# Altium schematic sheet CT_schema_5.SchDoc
size 520 x 457 mm
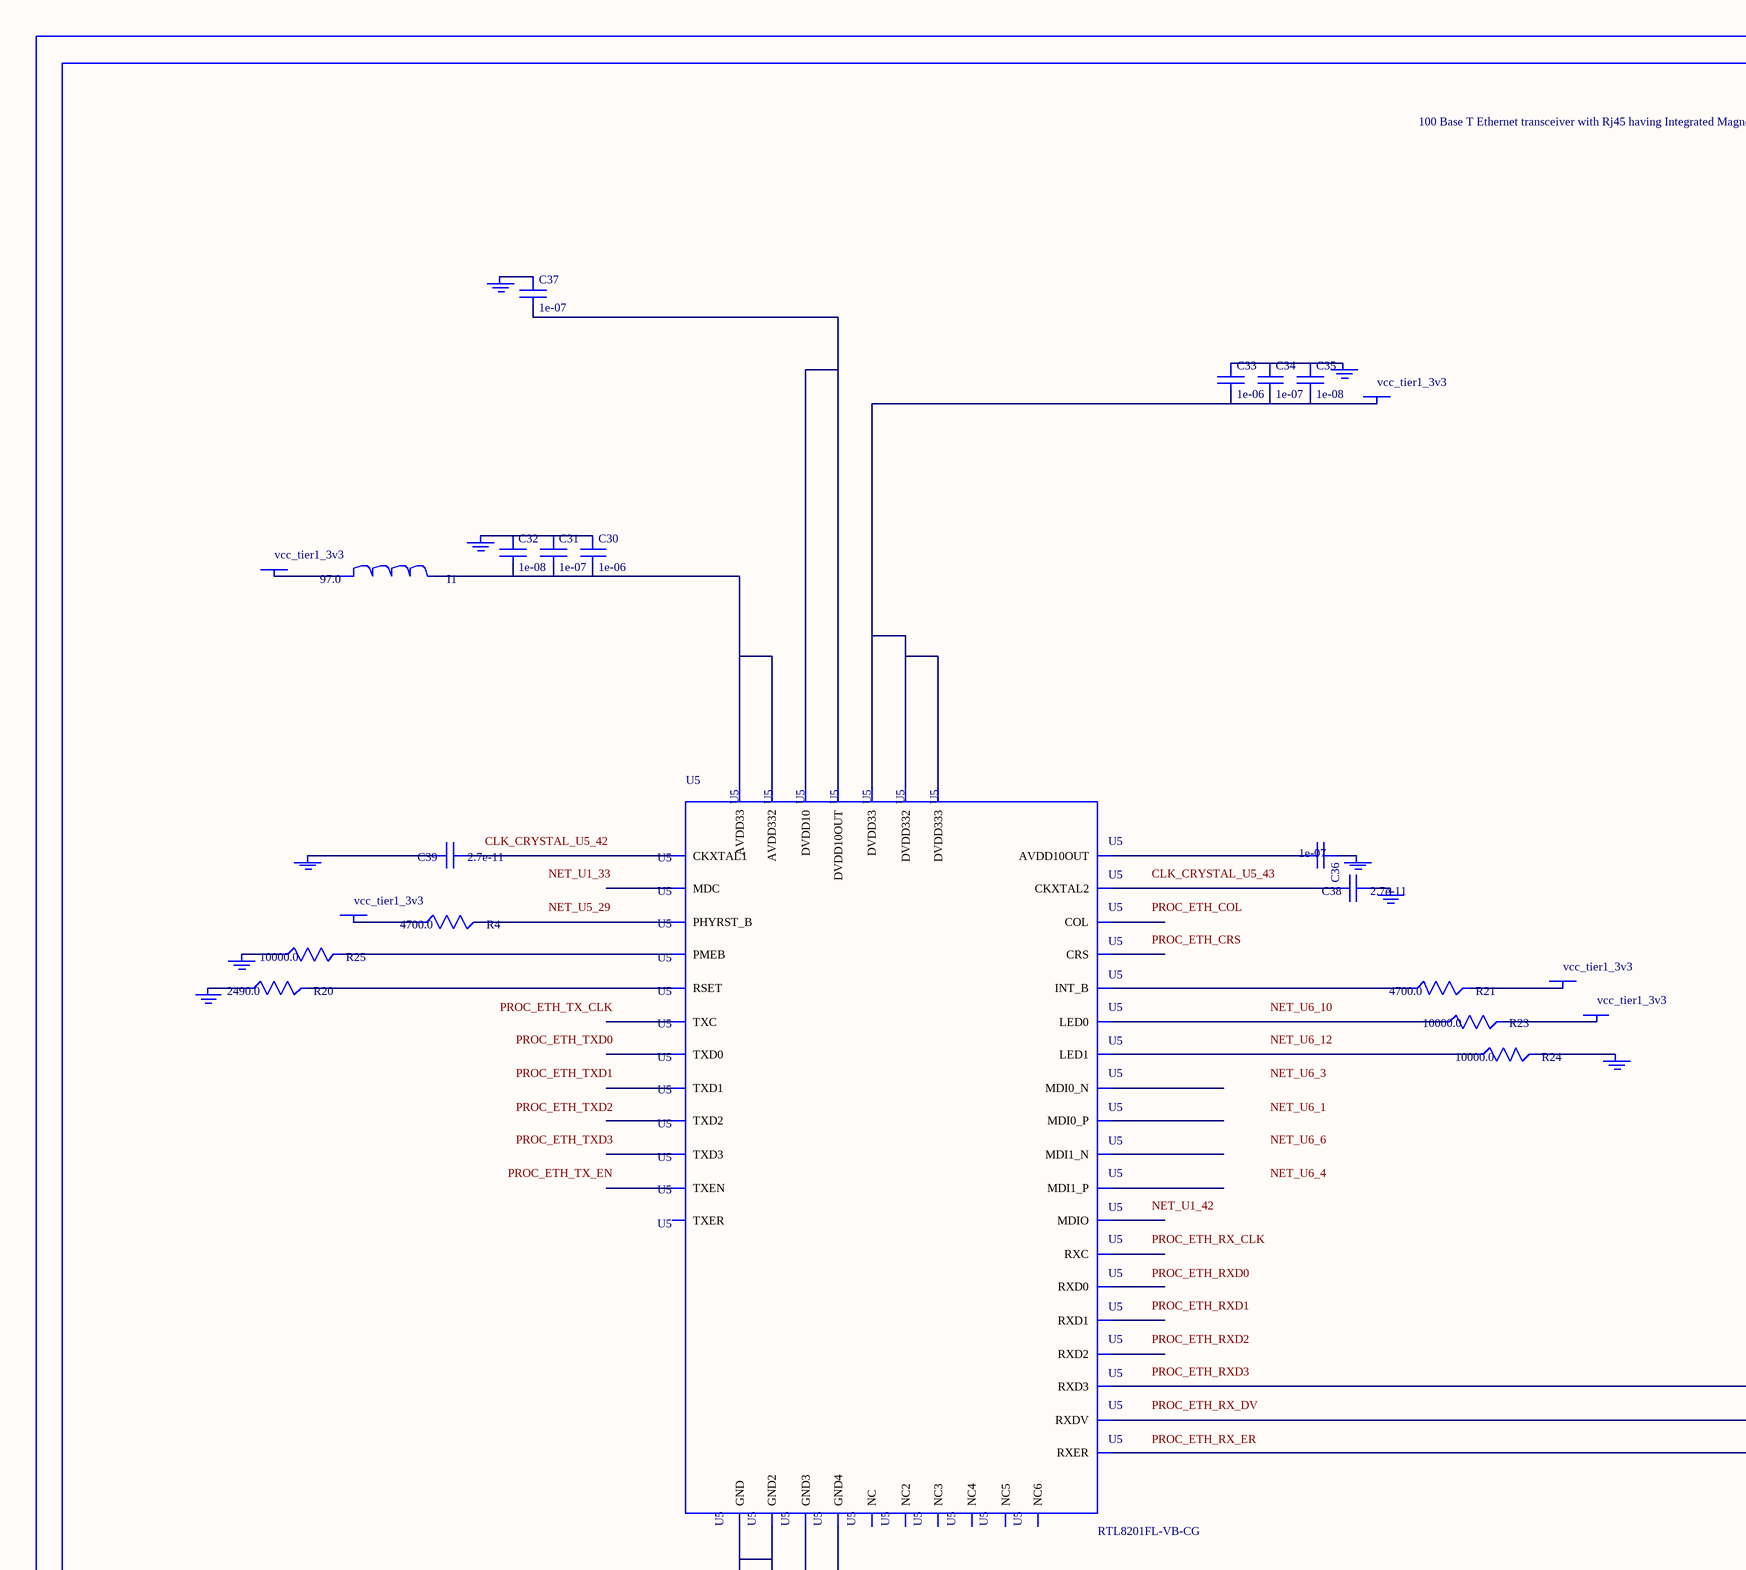
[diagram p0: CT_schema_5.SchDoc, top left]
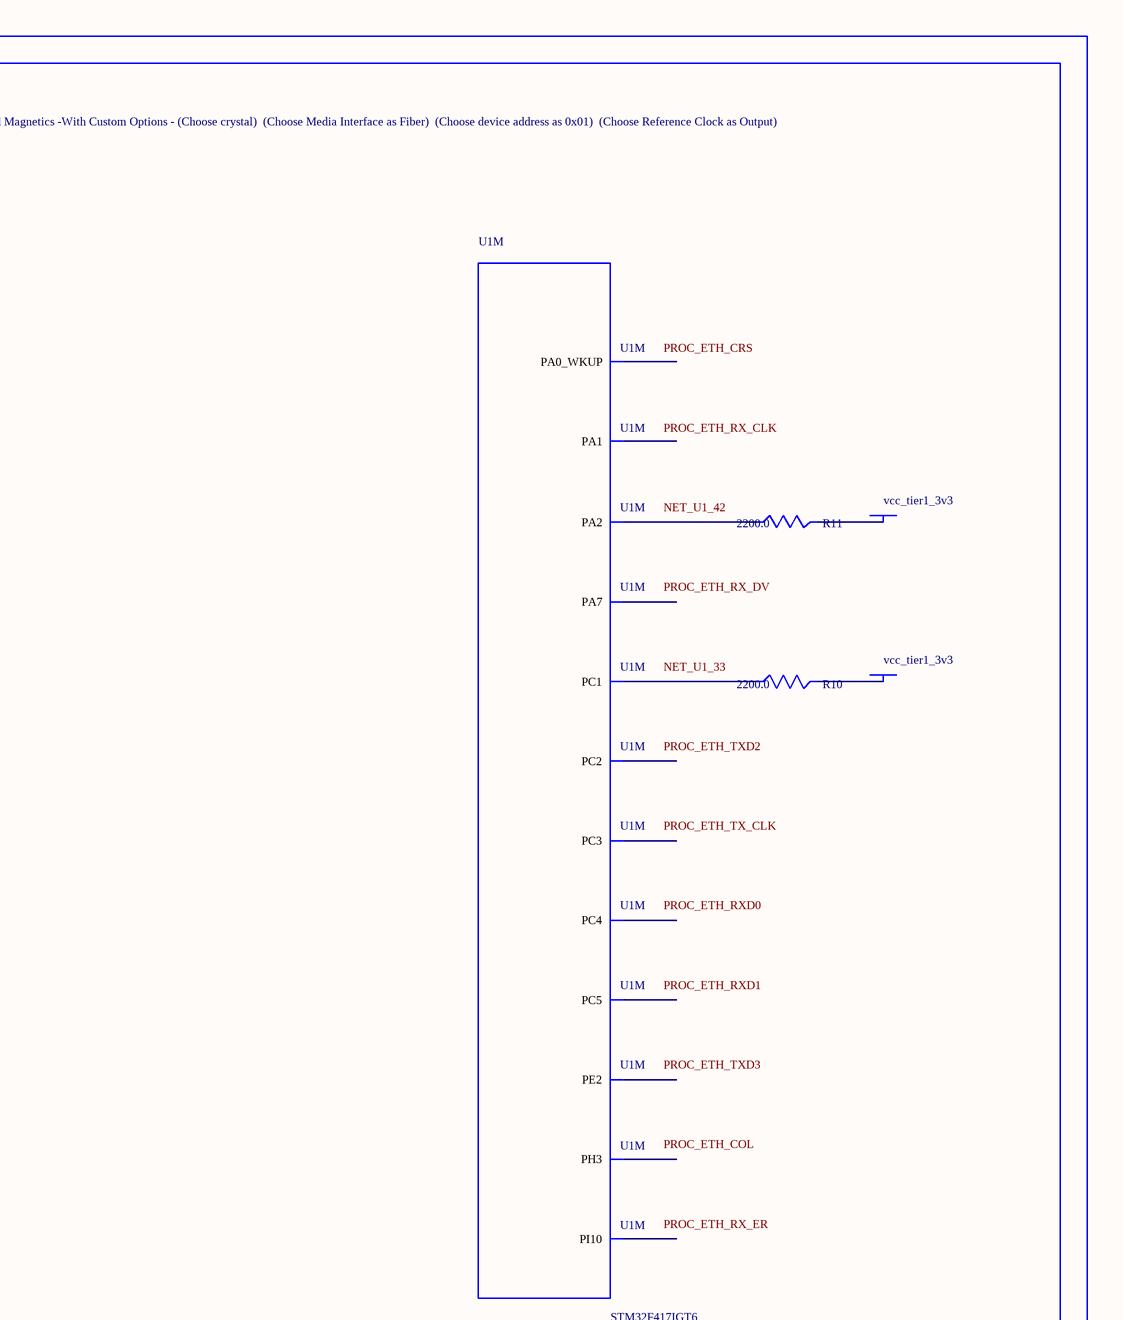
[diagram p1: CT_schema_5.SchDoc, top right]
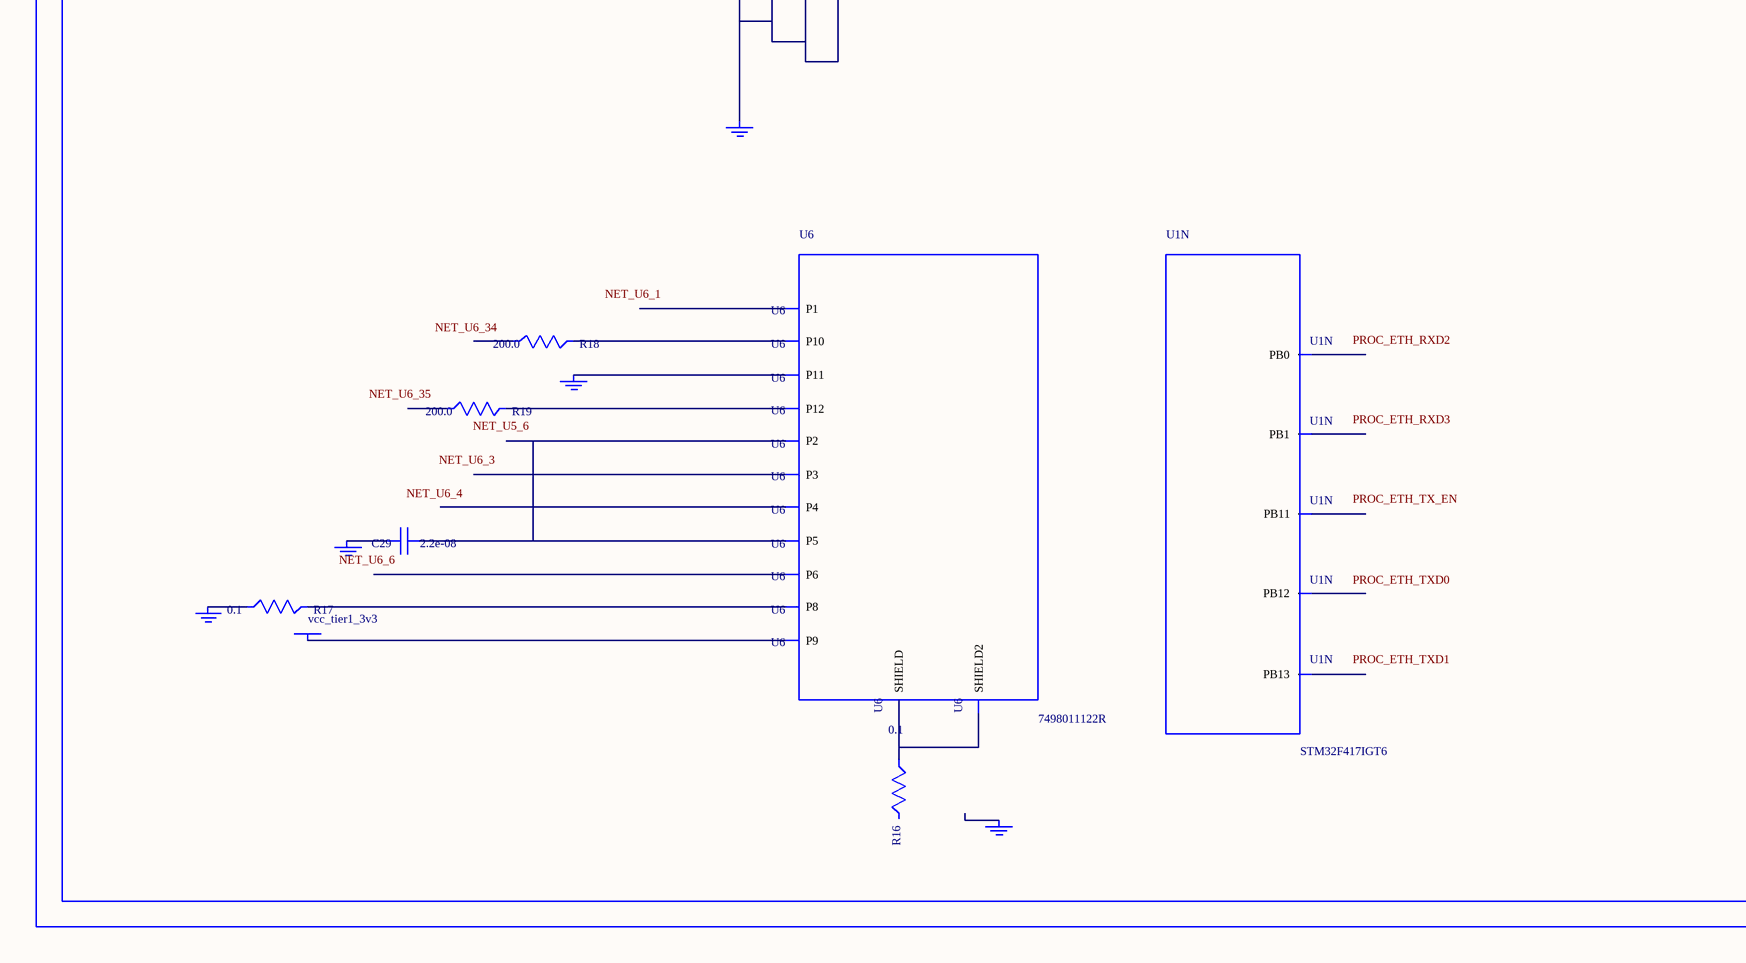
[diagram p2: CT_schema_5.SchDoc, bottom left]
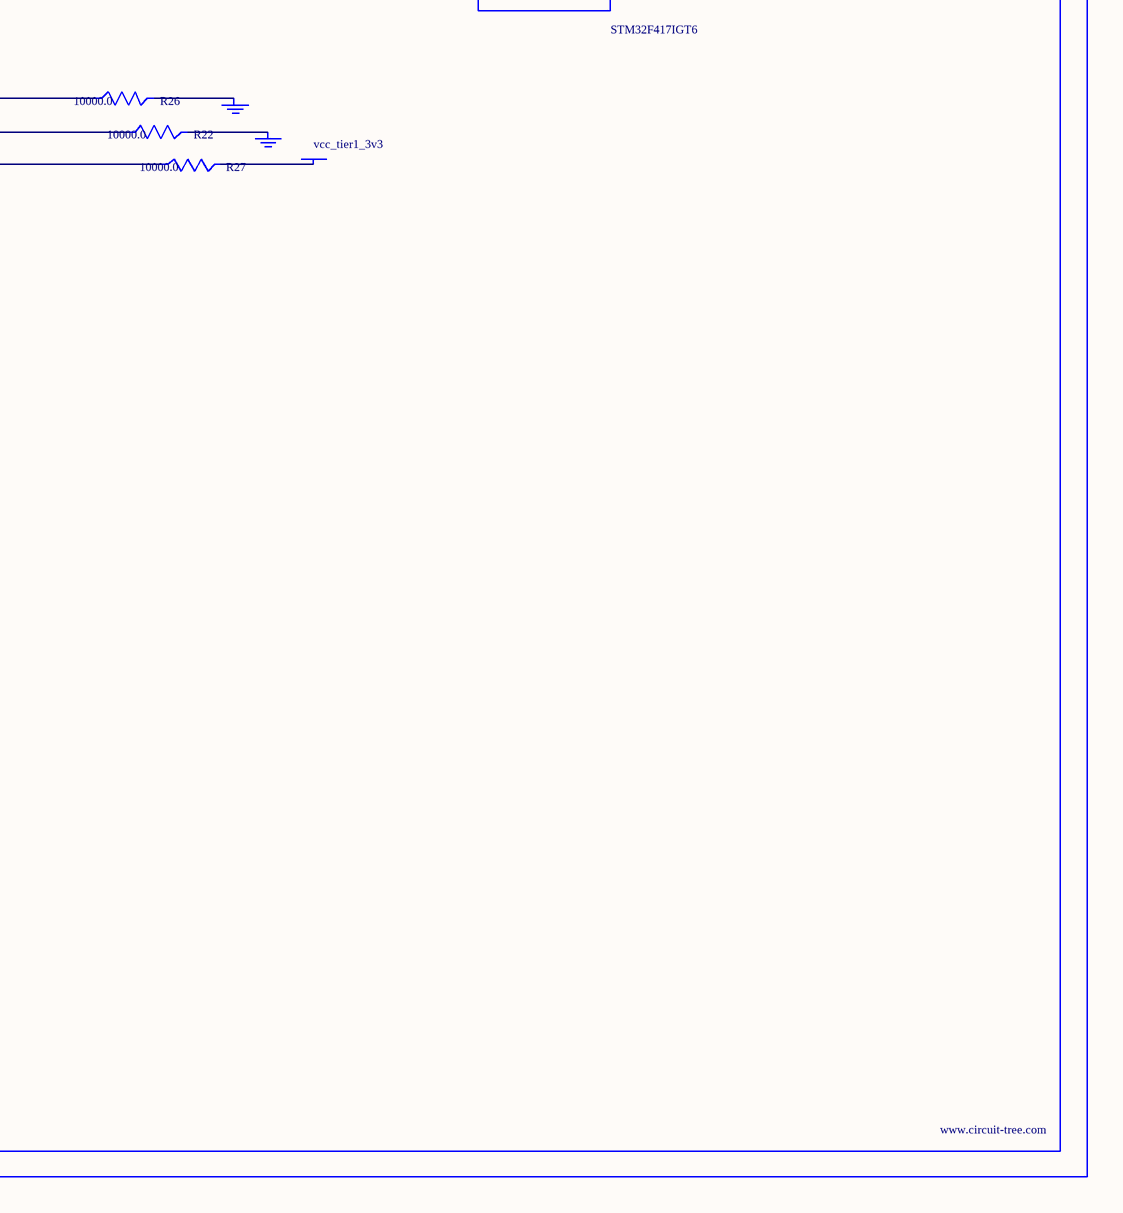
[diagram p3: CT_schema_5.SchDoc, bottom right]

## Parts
BORDER4  (no value)
C29  2.2e-08  [C0402]
C30  1e-06  [C0603]
C31  1e-07  [C0402]
C32  1e-08  [C0402]
C33  1e-06  [C0603]
C34  1e-07  [C0402]
C35  1e-08  [C0402]
C36  1e-07  [C0402]
C37  1e-07  [C0402]
C38  2.7e-11  [C0402]
C39  2.7e-11  [C0402]
GND_INSTANCE_4_0  (no value)
GND_INSTANCE_4_1  (no value)
GND_INSTANCE_4_2  (no value)
GND_INSTANCE_4_3  (no value)
GND_INSTANCE_4_4  (no value)
GND_INSTANCE_4_5  (no value)
GND_INSTANCE_4_6  (no value)
GND_INSTANCE_4_7  (no value)
GND_INSTANCE_4_8  (no value)
GND_INSTANCE_4_9  (no value)
GND_INSTANCE_4_10  (no value)
GND_INSTANCE_4_11  (no value)
GND_INSTANCE_4_12  (no value)
GND_INSTANCE_4_13  (no value)
GND_INSTANCE_4_14  (no value)
GND_INSTANCE_4_15  (no value)
I1  97.0  [R0603]
POWER_INSTANCE_4_0  vcc_tier1_3v3
POWER_INSTANCE_4_1  vcc_tier1_3v3
POWER_INSTANCE_4_2  vcc_tier1_3v3
POWER_INSTANCE_4_3  vcc_tier1_3v3
POWER_INSTANCE_4_4  vcc_tier1_3v3
POWER_INSTANCE_4_5  vcc_tier1_3v3
POWER_INSTANCE_4_6  vcc_tier1_3v3
POWER_INSTANCE_4_7  vcc_tier1_3v3
POWER_INSTANCE_4_8  vcc_tier1_3v3
R4  4700.0  [R0603]
R10  2200.0  [R0603]
R11  2200.0  [R0603]
R16  0.1  [R0603]
R17  0.1  [R0603]
R18  200.0  [R0603]
R19  200.0  [R0603]
R20  2490.0  [R0603]
R21  4700.0  [R0603]
R22  10000.0  [R0603]
R23  10000.0  [R0603]
R24  10000.0  [R0603]
R25  10000.0  [R0603]
R26  10000.0  [R0603]
R27  10000.0  [R0603]
U1  STM32F417IGT6  [LQFP176]  (parts M,N of 16)
U5  RTL8201FL-VB-CG  [RTL8201FL-VB-CG]
U6  7498011122R  [7498011122R]

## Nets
NetC29_1: C29.1 U6.2(P2) U6.5(P5)
NetC29_2: C29.2 GND_INSTANCE_4_12.0(GND)
NetC30_1: C30.1 C31.1 C32.1 GND_INSTANCE_4_0.0(GND)
NetC30_2: C30.2 C31.2 C32.2 I1.2 U5.6(AVDD33) U5.41(AVDD332)
NetC33_1: C33.1 C34.1 C35.1 GND_INSTANCE_4_3.0(GND)
NetC33_2: C33.2 C34.2 C35.2 POWER_INSTANCE_4_1.0(PWR) U5.15(DVDD33) U5.21(DVDD332) U5.37(DVDD333)
NetC36_1: C36.1 GND_INSTANCE_4_10.0(GND)
NetC36_2: C36.2 U5.48(AVDD10OUT)
NetC37_1: C37.1 GND_INSTANCE_4_6.0(GND)
NetC37_2: C37.2 U5.28(DVDD10) U5.40(DVDD10OUT)
NetC38_1: C38.1 GND_INSTANCE_4_8.0(GND)
NetC38_2: C38.2 U5.43(CKXTAL2)
NetC39_1: C39.1 U5.42(CKXTAL1)
NetC39_2: C39.2 GND_INSTANCE_4_7.0(GND)
NetGND_INSTANCE_4_1_0: GND_INSTANCE_4_1.0(GND) R25.1
NetGND_INSTANCE_4_2_0: GND_INSTANCE_4_2.0(GND) R22.2
NetGND_INSTANCE_4_4_0: GND_INSTANCE_4_4.0(GND) R26.2
NetGND_INSTANCE_4_5_0: GND_INSTANCE_4_5.0(GND) R24.2
NetGND_INSTANCE_4_9_0: GND_INSTANCE_4_9.0(GND) R20.1
NetGND_INSTANCE_4_11_0: GND_INSTANCE_4_11.0(GND) U5.7(GND) U5.20(GND2) U5.33(GND3) U5.47(GND4)
NetGND_INSTANCE_4_13_0: GND_INSTANCE_4_13.0(GND) R17.1
NetGND_INSTANCE_4_14_0: GND_INSTANCE_4_14.0(GND) U6.11(P11)
NetI1_1: I1.1 POWER_INSTANCE_4_0.0(PWR)
NetPOWER_INSTANCE_4_2_0: POWER_INSTANCE_4_2.0(PWR) R21.2
NetPOWER_INSTANCE_4_3_0: POWER_INSTANCE_4_3.0(PWR) R23.2
NetPOWER_INSTANCE_4_4_0: POWER_INSTANCE_4_4.0(PWR) R27.2
NetPOWER_INSTANCE_4_5_0: POWER_INSTANCE_4_5.0(PWR) R4.1
NetPOWER_INSTANCE_4_6_0: POWER_INSTANCE_4_6.0(PWR) R10.2
NetPOWER_INSTANCE_4_7_0: POWER_INSTANCE_4_7.0(PWR) R11.2
NetPOWER_INSTANCE_4_8_0: POWER_INSTANCE_4_8.0(PWR) U6.9(P9)
NetR4_2: R4.2 U5.29(PHYRST_B)
NetR10_1: R10.1 U1.33(PC1)
NetR11_1: R11.1 U1.42(PA2)
NetR16_1: R16.1 U6.13(SHIELD) U6.14(SHIELD2)
NetR17_2: R17.2 U6.8(P8)
NetR18_2: R18.2 U6.10(P10)
NetR19_2: R19.2 U6.12(P12)
NetR20_2: R20.2 U5.46(RSET)
NetR21_1: R21.1 U5.32(INT_B)
NetR22_1: R22.1 U5.13(RXDV)
NetR23_1: R23.1 U5.34(LED0)
NetR24_1: R24.1 U5.35(LED1)
NetR25_2: R25.2 U5.10(PMEB)
NetR26_1: R26.1 U5.18(RXD3)
NetR27_1: R27.1 U5.39(RXER)

Not connected (* = marked no-connect by the designer): GND_INSTANCE_4_15 0(GND); R16 2; R18 1; R19 1; U1 1(PE2) 12(PI10) 34(PC2) 35(PC3) 40(PA0_WKUP) 41(PA1) 44(PH3) 53(PA7) 54(PC4) 55(PC5) 56(PB0) 57(PB1) 80(PB11) 92(PB12) 93(PB13); U5 1(MDI0_P) 2(MDI0_N) 3(NC) 4(MDI1_P) 5(MDI1_N) 8(NC2) 9(NC3) 11(NC4) 12(TXER) 14(RXD0) 16(RXD1) 17(RXD2) 19(RXC) 22(TXC) 23(TXD0) 24(TXD1) 25(TXD2) 26(TXD3) 27(TXEN) 30(MDC) 31(MDIO) 36(CRS) 38(COL) 44(NC5) 45(NC6); U6 1(P1) 3(P3) 4(P4) 6(P6)

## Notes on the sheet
- Labels drawn without touching a wire or pin: CLK_CRYSTAL_U5_42, CLK_CRYSTAL_U5_43, NET_U1_33, NET_U1_42, NET_U5_6, NET_U5_29, NET_U6_1, NET_U6_3, NET_U6_4, NET_U6_6, NET_U6_10, NET_U6_12, NET_U6_34, NET_U6_35, PROC_ETH_COL, PROC_ETH_CRS, PROC_ETH_RX_CLK, PROC_ETH_RX_DV, PROC_ETH_RX_ER, PROC_ETH_RXD0, PROC_ETH_RXD1, PROC_ETH_RXD2, PROC_ETH_RXD3, PROC_ETH_TX_CLK, PROC_ETH_TX_EN, PROC_ETH_TXD0, PROC_ETH_TXD1, PROC_ETH_TXD2, PROC_ETH_TXD3

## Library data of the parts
BORDER4 = BORDER_PAGE4
C29 = C0402C223K3RAC
C30 C33 = C0603C105K3RACTU
C31 C34 C36 C37 = C0402C104K3RACTU
C32 C35 = C0402C103K3RAC
C38 C39 = C0402C270K3RAC
GND_INSTANCE_4_0-GND_INSTANCE_4_15 = GND
I1 = I1
POWER_INSTANCE_4_0-POWER_INSTANCE_4_8 = PWR
R4 R21 = RC0603JR-074K7L
R10 R11 = RC0603JR-072K2L
R16 R17 = ERJ-3RSFR10V
R18 R19 = RC0603JR-07200RL
R20 = ERA-3AED2490V
R22-R27 = RC0603JR-0710KL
